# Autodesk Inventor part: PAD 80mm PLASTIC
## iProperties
Created: 2007-03
Part Number: PAD 80mm PLASTIC
Document SubType Name: Modeling
Designer: Andy Moles
Material: ABS Plastic
Density: 1.06 g/cm^3
Mass: 40.5634 g
Surface Area: 136.746 cm^2
Volume: 38.2674 cm^3
Author: Andy Moles
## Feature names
1. Revolution1
2. Extrusion1
3. Extrusion2
